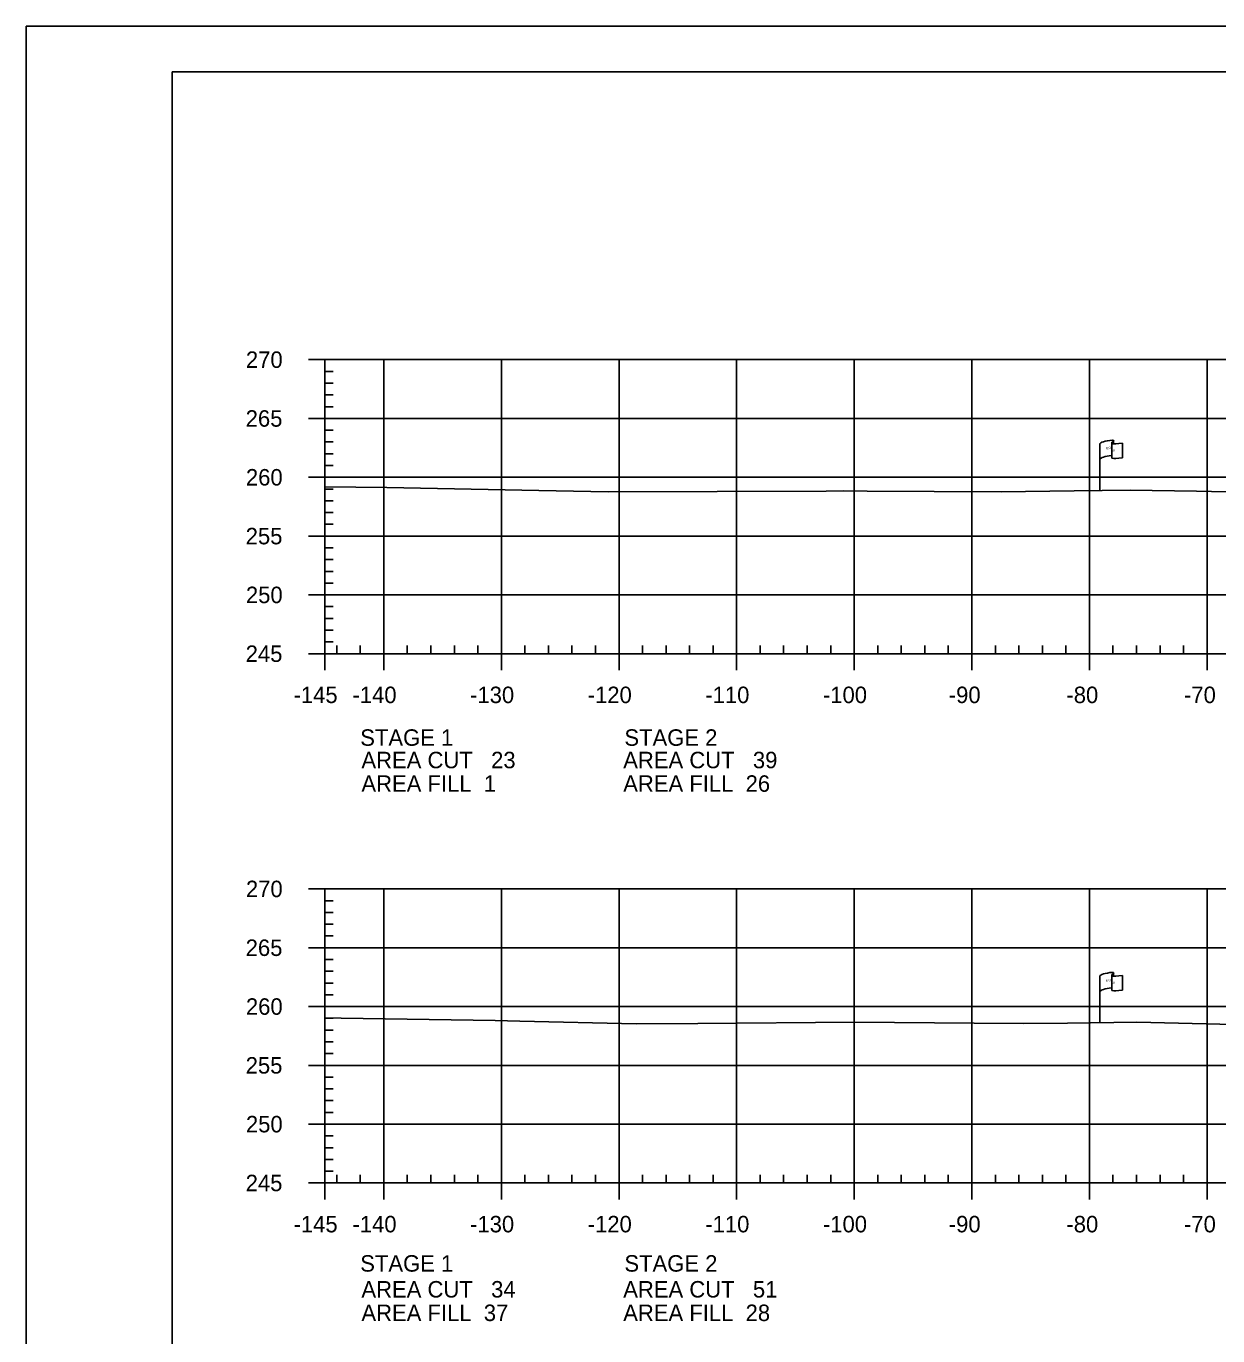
# Model space of a CAD drawing. Extents: x 1365647 to 1367999, y 387113 to 400173.
# Drawn here: x 1365723.7 to 1365825, y 387261.4 to 387372.7 of the extents above; entities that cross this region are included whole.
import ezdxf

# ---------------------------------------------------------------- set-up
doc = ezdxf.new("R2010")
doc.units = 0
for name, color, linetype in [('E_Existing ROW', 7, 'Continuous'), ('R_Axis', 7, 'Continuous'), ('R_Axis Annot', 7, 'Continuous'), ('R_Border', 7, 'Continuous'), ('R_Exist Surface', 7, 'Continuous'), ('R_Grid', 7, 'Continuous'), ('R_No Plot', 7, 'Continuous')]:
    doc.layers.add(name, color=color, linetype=linetype)

msp = doc.modelspace()

# ---------------------------------------------------------------- linework, layer by layer
at = {"layer": 'E_Existing ROW'}
for p, q in [((1365814.98, 387333.26), (1365814.98, 387337.21)), ((1365815.98, 387337.31), (1365815.98, 387337.29)), ((1365815.98, 387337.29), (1365815.98, 387336.07)), ((1365816.14, 387337.46), (1365816.14, 387337.22)), ((1365816.91, 387337.27), (1365816.91, 387336.03)), ((1365814.98, 387288), (1365814.98, 387291.96)), ((1365815.98, 387292.05), (1365815.98, 387292.04)), ((1365815.98, 387292.04), (1365815.98, 387290.81)), ((1365816.14, 387292.21), (1365816.14, 387291.97)), ((1365816.91, 387292.01), (1365816.91, 387290.77))]:
    msp.add_line(p, q, dxfattribs=at)
for centre, radius, start, end in [((1365816.05, 387337.31), 0.078, 88.6458, 274.2828), ((1365816.07, 387337.46), 0.0783, 263.0712, 93.9564), ((1365816.05, 387336.07), 0.0783, 180, 273.9564), ((1365816.05, 387292.05), 0.078, 88.6458, 274.2828), ((1365816.07, 387292.21), 0.0783, 263.0712, 93.9564), ((1365816.05, 387290.81), 0.0783, 180, 273.9564)]:
    msp.add_arc(centre, radius, start, end, dxfattribs=at)
for centre, major_axis, ratio, start_param, end_param in [((1365816.56, 387337.25), (-1.58, -0.04), 0.19887, 5.030368, 6.283185), ((1365817.27, 387337.37), (-1.23, -0.13), 0.052933, 0.159456, 1.268315), ((1365816.56, 387335.94), (-1.58, -0.04), 0.19887, 5.083035, 6.194897), ((1365817.27, 387336.13), (-1.23, -0.13), 0.052933, 0.159456, 1.268315), ((1365816.56, 387292), (-1.58, -0.04), 0.19887, 5.030368, 6.283185), ((1365817.27, 387292.11), (-1.23, -0.13), 0.052933, 0.159456, 1.268315), ((1365816.56, 387290.68), (-1.58, -0.04), 0.19887, 5.083035, 6.194897), ((1365817.27, 387290.87), (-1.23, -0.13), 0.052933, 0.159456, 1.268315)]:
    msp.add_ellipse(centre, major_axis=major_axis, ratio=ratio, start_param=start_param, end_param=end_param, dxfattribs=at)
at = {"layer": 'R_Axis'}
for p, q in [((1365747.69, 387344.38), (1365749.09, 387344.38)), ((1365749.09, 387319.38), (1365749.09, 387344.38)), ((1365749.09, 387343.38), (1365749.79, 387343.38)), ((1365749.09, 387342.38), (1365749.79, 387342.38)), ((1365749.09, 387341.38), (1365749.79, 387341.38)), ((1365749.09, 387340.38), (1365749.79, 387340.38)), ((1365747.69, 387339.38), (1365749.09, 387339.38)), ((1365749.09, 387338.38), (1365749.79, 387338.38)), ((1365749.09, 387337.38), (1365749.79, 387337.38)), ((1365749.09, 387336.38), (1365749.79, 387336.38)), ((1365749.09, 387335.38), (1365749.79, 387335.38)), ((1365747.69, 387334.38), (1365749.09, 387334.38)), ((1365749.09, 387333.38), (1365749.79, 387333.38)), ((1365749.09, 387332.38), (1365749.79, 387332.38)), ((1365749.09, 387331.38), (1365749.79, 387331.38)), ((1365749.09, 387330.38), (1365749.79, 387330.38)), ((1365747.69, 387329.38), (1365749.09, 387329.38)), ((1365749.09, 387328.38), (1365749.79, 387328.38)), ((1365749.09, 387327.38), (1365749.79, 387327.38)), ((1365749.09, 387326.38), (1365749.79, 387326.38)), ((1365749.09, 387325.38), (1365749.79, 387325.38)), ((1365747.69, 387324.38), (1365749.09, 387324.38)), ((1365749.09, 387323.38), (1365749.79, 387323.38)), ((1365749.09, 387322.38), (1365749.79, 387322.38)), ((1365749.09, 387321.38), (1365749.79, 387321.38)), ((1365749.09, 387320.38), (1365749.79, 387320.38)), ((1365747.69, 387319.38), (1365749.09, 387319.38)), ((1365749.09, 387319.38), (1365749.09, 387320.08)), ((1365749.09, 387319.38), (1366039.09, 387319.38)), ((1365749.09, 387317.98), (1365749.09, 387319.38)), ((1365750.09, 387319.38), (1365750.09, 387320.08)), ((1365752.09, 387319.38), (1365752.09, 387320.08)), ((1365754.09, 387317.98), (1365754.09, 387319.38)), ((1365756.09, 387319.38), (1365756.09, 387320.08)), ((1365758.09, 387319.38), (1365758.09, 387320.08)), ((1365760.09, 387319.38), (1365760.09, 387320.08)), ((1365762.09, 387319.38), (1365762.09, 387320.08)), ((1365764.09, 387317.98), (1365764.09, 387319.38)), ((1365766.09, 387319.38), (1365766.09, 387320.08)), ((1365768.09, 387319.38), (1365768.09, 387320.08)), ((1365770.09, 387319.38), (1365770.09, 387320.08)), ((1365772.09, 387319.38), (1365772.09, 387320.08)), ((1365774.09, 387317.98), (1365774.09, 387319.38)), ((1365776.09, 387319.38), (1365776.09, 387320.08)), ((1365778.09, 387319.38), (1365778.09, 387320.08)), ((1365780.09, 387319.38), (1365780.09, 387320.08)), ((1365782.09, 387319.38), (1365782.09, 387320.08)), ((1365784.09, 387317.98), (1365784.09, 387319.38)), ((1365786.09, 387319.38), (1365786.09, 387320.08)), ((1365788.09, 387319.38), (1365788.09, 387320.08)), ((1365790.09, 387319.38), (1365790.09, 387320.08)), ((1365792.09, 387319.38), (1365792.09, 387320.08)), ((1365794.09, 387317.98), (1365794.09, 387319.38)), ((1365796.09, 387319.38), (1365796.09, 387320.08)), ((1365798.09, 387319.38), (1365798.09, 387320.08)), ((1365800.09, 387319.38), (1365800.09, 387320.08)), ((1365802.09, 387319.38), (1365802.09, 387320.08)), ((1365804.09, 387317.98), (1365804.09, 387319.38)), ((1365806.09, 387319.38), (1365806.09, 387320.08)), ((1365808.09, 387319.38), (1365808.09, 387320.08)), ((1365810.09, 387319.38), (1365810.09, 387320.08)), ((1365812.09, 387319.38), (1365812.09, 387320.08)), ((1365814.09, 387317.98), (1365814.09, 387319.38)), ((1365816.09, 387319.38), (1365816.09, 387320.08)), ((1365818.09, 387319.38), (1365818.09, 387320.08)), ((1365820.09, 387319.38), (1365820.09, 387320.08)), ((1365822.09, 387319.38), (1365822.09, 387320.08)), ((1365824.09, 387317.98), (1365824.09, 387319.38)), ((1365747.69, 387299.38), (1365749.09, 387299.38)), ((1365749.09, 387274.38), (1365749.09, 387299.38)), ((1365749.09, 387298.38), (1365749.79, 387298.38)), ((1365749.09, 387297.38), (1365749.79, 387297.38)), ((1365749.09, 387296.38), (1365749.79, 387296.38)), ((1365749.09, 387295.38), (1365749.79, 387295.38)), ((1365747.69, 387294.38), (1365749.09, 387294.38)), ((1365749.09, 387293.38), (1365749.79, 387293.38)), ((1365749.09, 387292.38), (1365749.79, 387292.38)), ((1365749.09, 387291.38), (1365749.79, 387291.38)), ((1365749.09, 387290.38), (1365749.79, 387290.38)), ((1365747.69, 387289.38), (1365749.09, 387289.38)), ((1365749.09, 387288.38), (1365749.79, 387288.38)), ((1365749.09, 387287.38), (1365749.79, 387287.38)), ((1365749.09, 387286.38), (1365749.79, 387286.38)), ((1365749.09, 387285.38), (1365749.79, 387285.38)), ((1365747.69, 387284.38), (1365749.09, 387284.38)), ((1365749.09, 387283.38), (1365749.79, 387283.38)), ((1365749.09, 387282.38), (1365749.79, 387282.38)), ((1365749.09, 387281.38), (1365749.79, 387281.38)), ((1365749.09, 387280.38), (1365749.79, 387280.38)), ((1365747.69, 387279.38), (1365749.09, 387279.38)), ((1365749.09, 387278.38), (1365749.79, 387278.38)), ((1365749.09, 387277.38), (1365749.79, 387277.38)), ((1365749.09, 387276.38), (1365749.79, 387276.38)), ((1365749.09, 387275.38), (1365749.79, 387275.38)), ((1365749.09, 387274.38), (1365749.09, 387275.08)), ((1365750.09, 387274.38), (1365750.09, 387275.08)), ((1365752.09, 387274.38), (1365752.09, 387275.08)), ((1365756.09, 387274.38), (1365756.09, 387275.08)), ((1365758.09, 387274.38), (1365758.09, 387275.08)), ((1365760.09, 387274.38), (1365760.09, 387275.08)), ((1365762.09, 387274.38), (1365762.09, 387275.08)), ((1365766.09, 387274.38), (1365766.09, 387275.08)), ((1365768.09, 387274.38), (1365768.09, 387275.08)), ((1365770.09, 387274.38), (1365770.09, 387275.08)), ((1365772.09, 387274.38), (1365772.09, 387275.08)), ((1365776.09, 387274.38), (1365776.09, 387275.08)), ((1365778.09, 387274.38), (1365778.09, 387275.08)), ((1365780.09, 387274.38), (1365780.09, 387275.08)), ((1365782.09, 387274.38), (1365782.09, 387275.08)), ((1365786.09, 387274.38), (1365786.09, 387275.08)), ((1365788.09, 387274.38), (1365788.09, 387275.08)), ((1365790.09, 387274.38), (1365790.09, 387275.08)), ((1365792.09, 387274.38), (1365792.09, 387275.08)), ((1365796.09, 387274.38), (1365796.09, 387275.08)), ((1365798.09, 387274.38), (1365798.09, 387275.08)), ((1365800.09, 387274.38), (1365800.09, 387275.08)), ((1365802.09, 387274.38), (1365802.09, 387275.08)), ((1365806.09, 387274.38), (1365806.09, 387275.08)), ((1365808.09, 387274.38), (1365808.09, 387275.08)), ((1365810.09, 387274.38), (1365810.09, 387275.08)), ((1365812.09, 387274.38), (1365812.09, 387275.08)), ((1365816.09, 387274.38), (1365816.09, 387275.08)), ((1365818.09, 387274.38), (1365818.09, 387275.08)), ((1365820.09, 387274.38), (1365820.09, 387275.08)), ((1365822.09, 387274.38), (1365822.09, 387275.08)), ((1365747.69, 387274.38), (1365749.09, 387274.38)), ((1365749.09, 387274.38), (1366039.09, 387274.38)), ((1365749.09, 387272.98), (1365749.09, 387274.38)), ((1365754.09, 387272.98), (1365754.09, 387274.38)), ((1365764.09, 387272.98), (1365764.09, 387274.38)), ((1365774.09, 387272.98), (1365774.09, 387274.38)), ((1365784.09, 387272.98), (1365784.09, 387274.38)), ((1365794.09, 387272.98), (1365794.09, 387274.38)), ((1365804.09, 387272.98), (1365804.09, 387274.38)), ((1365814.09, 387272.98), (1365814.09, 387274.38)), ((1365824.09, 387272.98), (1365824.09, 387274.38))]:
    msp.add_line(p, q, dxfattribs=at)
at = {"layer": 'R_Border'}
for p, q in [((1365736.09, 387368.84), (1366052.27, 387368.84)), ((1365736.09, 387163.38), (1365736.09, 387368.84))]:
    msp.add_line(p, q, dxfattribs=at)
at = {"layer": 'R_Exist Surface'}
for points in [[(1365749.09, 387333.56), (1365754.34, 387333.52), (1365767.26, 387333.26), (1365773.18, 387333.13), (1365791.71, 387333.21), (1365793.14, 387333.22), (1365795.2, 387333.21), (1365806.57, 387333.15), (1365812.79, 387333.23), (1365817.56, 387333.29), (1365823.2, 387333.2), (1365832.06, 387333)], [(1365749.09, 387288.41), (1365750.48, 387288.39), (1365763.57, 387288.19), (1365765.66, 387288.15), (1365775.55, 387287.91), (1365780.79, 387287.94), (1365794.13, 387288.06), (1365804.29, 387287.96), (1365808.44, 387287.93), (1365812.23, 387287.97), (1365818.13, 387288.04), (1365826.36, 387287.85)]]:
    msp.add_lwpolyline(points, dxfattribs=at)
at = {"layer": 'R_Grid'}
for p, q in [((1365749.09, 387344.38), (1366039.09, 387344.38)), ((1365749.09, 387319.38), (1365749.09, 387344.38)), ((1365754.09, 387319.38), (1365754.09, 387344.38)), ((1365764.09, 387319.38), (1365764.09, 387344.38)), ((1365774.09, 387319.38), (1365774.09, 387344.38)), ((1365784.09, 387319.38), (1365784.09, 387344.38)), ((1365794.09, 387319.38), (1365794.09, 387344.38)), ((1365804.09, 387319.38), (1365804.09, 387344.38)), ((1365814.09, 387319.38), (1365814.09, 387344.38)), ((1365824.09, 387319.38), (1365824.09, 387344.38)), ((1365749.09, 387339.38), (1366039.09, 387339.38)), ((1365749.09, 387334.38), (1366039.09, 387334.38)), ((1365749.09, 387329.38), (1366039.09, 387329.38)), ((1365749.09, 387324.38), (1366039.09, 387324.38)), ((1365749.09, 387319.38), (1366039.09, 387319.38)), ((1365749.09, 387299.38), (1366039.09, 387299.38)), ((1365749.09, 387274.38), (1365749.09, 387299.38)), ((1365754.09, 387274.38), (1365754.09, 387299.38)), ((1365764.09, 387274.38), (1365764.09, 387299.38)), ((1365774.09, 387274.38), (1365774.09, 387299.38)), ((1365784.09, 387274.38), (1365784.09, 387299.38)), ((1365794.09, 387274.38), (1365794.09, 387299.38)), ((1365804.09, 387274.38), (1365804.09, 387299.38)), ((1365814.09, 387274.38), (1365814.09, 387299.38)), ((1365824.09, 387274.38), (1365824.09, 387299.38)), ((1365749.09, 387294.38), (1366039.09, 387294.38)), ((1365749.09, 387289.38), (1366039.09, 387289.38)), ((1365749.09, 387284.38), (1366039.09, 387284.38)), ((1365749.09, 387279.38), (1366039.09, 387279.38)), ((1365749.09, 387274.38), (1366039.09, 387274.38))]:
    msp.add_line(p, q, dxfattribs=at)
at = {"layer": 'R_No Plot'}
msp.add_line((1365723.69, 387372.73), (1366057.03, 387372.73), dxfattribs=at)
msp.add_lwpolyline([(1365723.69, 387372.73), (1366057.03, 387372.73), (1366057.03, 387159.4), (1365723.69, 387159.4)], close=True, dxfattribs=at)

# ---------------------------------------------------------------- texts
at = {"layer": 'E_Existing ROW'}
for s, height, rotation, p in [('R ', 0.2, 9.9884, (1365815.5, 387336.71)), (' O', 0.2, 9.9884, (1365815.65, 387336.76)), ('DWB 11-9-07', 0.001, 90, (1365816.14, 387337.22)), ('W', 0.2, 351.1788, (1365815.98, 387336.59)), ('DWB 11-9-07', 0.001, 5.0717, (1365816.9, 387336.03)), ('DWB 11-9-07', 0.001, 90, (1365814.98, 387333.26)), ('R ', 0.2, 9.9884, (1365815.5, 387291.46)), (' O', 0.2, 9.9884, (1365815.65, 387291.5)), ('W', 0.2, 351.1788, (1365815.98, 387291.33)), ('DWB 11-9-07', 0.001, 90, (1365816.14, 387291.97)), ('DWB 11-9-07', 0.001, 5.0717, (1365816.9, 387290.77)), ('DWB 11-9-07', 0.001, 90, (1365814.98, 387288))]:
    msp.add_text(s, height=height, rotation=rotation, dxfattribs=at).set_placement(p)
at = {"layer": 'R_Axis Annot'}
for s, p in [('270', (1365742.37, 387343.68)), ('265', (1365742.35, 387338.68)), ('260', (1365742.37, 387333.68)), ('255', (1365742.35, 387328.68)), ('250', (1365742.37, 387323.68)), ('245', (1365742.35, 387318.68)), ('-145', (1365746.42, 387315.18)), ('-140', (1365751.43, 387315.18)), ('-130', (1365761.43, 387315.18)), ('-120', (1365771.43, 387315.18)), ('-110', (1365781.43, 387315.18)), ('-100', (1365791.43, 387315.18)), ('-90', (1365802.13, 387315.18)), ('-80', (1365812.13, 387315.18)), ('-70', (1365822.13, 387315.18)), ('STAGE 1', (1365752.09, 387311.55)), ('STAGE 2', (1365774.55, 387311.55)), ('AREA CUT   23', (1365752.19, 387309.64)), ('AREA CUT   39', (1365774.45, 387309.64)), ('AREA FILL  1', (1365752.19, 387307.64)), ('AREA FILL  26', (1365774.45, 387307.64)), ('270', (1365742.37, 387298.68)), ('265', (1365742.35, 387293.68)), ('260', (1365742.37, 387288.68)), ('255', (1365742.35, 387283.68)), ('250', (1365742.37, 387278.68)), ('245', (1365742.35, 387273.68)), ('-145', (1365746.42, 387270.18)), ('-140', (1365751.43, 387270.18)), ('-130', (1365761.43, 387270.18)), ('-120', (1365771.43, 387270.18)), ('-110', (1365781.43, 387270.18)), ('-100', (1365791.43, 387270.18)), ('-90', (1365802.13, 387270.18)), ('-80', (1365812.13, 387270.18)), ('-70', (1365822.13, 387270.18)), ('STAGE 1', (1365752.09, 387266.84)), ('STAGE 2', (1365774.55, 387266.84)), ('AREA CUT   34', (1365752.19, 387264.64)), ('AREA CUT   51', (1365774.45, 387264.64)), ('AREA FILL  37', (1365752.19, 387262.64)), ('AREA FILL  28', (1365774.45, 387262.64))]:
    msp.add_text(s, height=1.4, dxfattribs=at).set_placement(p)

doc.saveas('drawing.dxf')
